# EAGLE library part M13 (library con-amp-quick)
AMP QUICK CONNECTOR
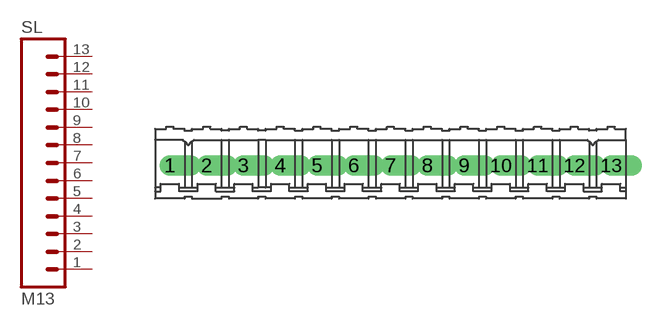
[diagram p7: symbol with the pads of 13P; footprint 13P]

Designator prefix SL

## M13  [13P]
1  1  pas
2  2  pas
3  3  pas
4  4  pas
5  5  pas
6  6  pas
7  7  pas
8  8  pas
9  9  pas
10  10  pas
11  11  pas
12  12  pas
13  13  pas

## Footprint 13P (pad centres in mm)
AMP QUICK CONNECTOR
drill 0.914 offset: 1 -15.24,0; 2 -12.7,0; 3 -10.16,0; 4 -7.62,0; 5 -5.08,0; 6 -2.54,0; 7 0,0; 8 2.54,0; 9 5.08,0; 10 7.62,0; 11 10.16,0; 12 12.7,0; 13 15.24,0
